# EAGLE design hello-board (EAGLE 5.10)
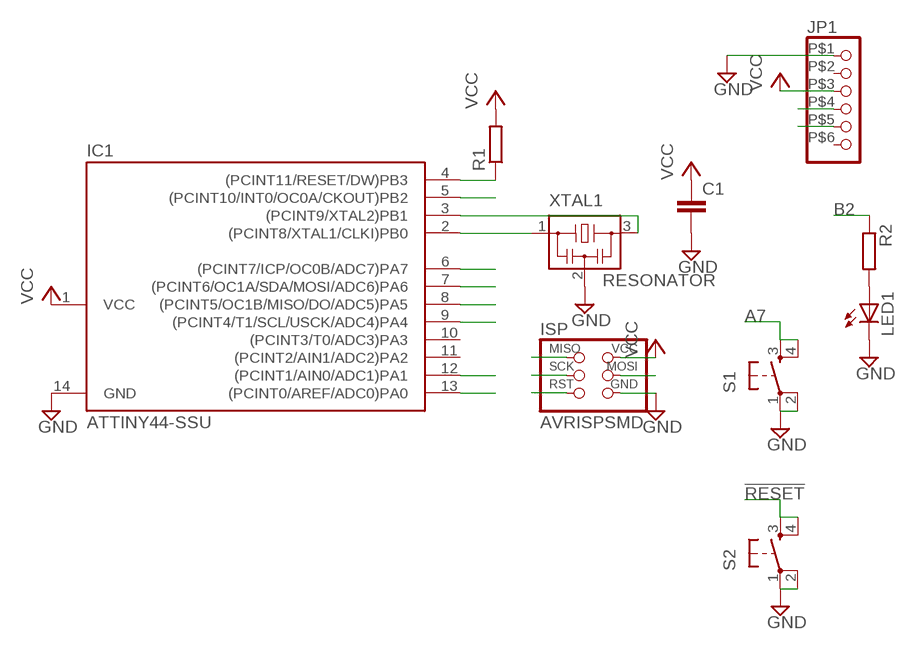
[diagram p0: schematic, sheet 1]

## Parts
C1  C-EUC1206  [C1206]
IC1  ATTINY44-SSU  [SOIC14]
ISP  AVRISPSMD  [2X03SMD]
JP1  PINHD-1X6SMD  [1X06SMD]
LED1  LEDCHIPLED_1206  [CHIPLED_1206]
R1  R-EU_R1206  [R1206]
R2  R-EU_R1206  [R1206]
S1  6MM_SWITCH6MM_SWITCH  [6MM_SWITCH]
S2  6MM_SWITCH6MM_SWITCH  [6MM_SWITCH]
XTAL1  RESONATOR  [EFOBM]

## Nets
!RESET: IC1.4((PCINT11/RESET/DW)PB3) ISP.5(RST) R1.1 S2.3(S) S2.4(S1)
A7: IC1.6((PCINT7/ICP/OC0B/ADC7)PA7) S1.3(S) S1.4(S1)
B2: IC1.5((PCINT10/INT0/OC0A/CKOUT)PB2) R2.1
GND: C1.2 IC1.14(GND) ISP.6(GND) JP1.P$1 LED1.C S1.1(P) S1.2(P1) S2.1(P) S2.2(P1) XTAL1.2
MISO: IC1.8((PCINT5/OC1B/MISO/DO/ADC5)PA5) ISP.1(MISO)
MOSI: IC1.7((PCINT6/OC1A/SDA/MOSI/ADC6)PA6) ISP.4(MOSI)
N$1: LED1.A R2.2
N$2: IC1.2((PCINT8/XTAL1/CLKI)PB0) XTAL1.1
N$3: IC1.3((PCINT9/XTAL2)PB1) XTAL1.3
RX: IC1.12((PCINT1/AIN0/ADC1)PA1) JP1.P$5
SCL: IC1.9((PCINT4/T1/SCL/USCK/ADC4)PA4) ISP.3(SCK)
TX: IC1.13((PCINT0/AREF/ADC0)PA0) JP1.P$4
VCC: C1.1 IC1.1(VCC) ISP.2(VCC) JP1.P$3 R1.2
Unconnected: IC1.10((PCINT3/T0/ADC3)PA3) IC1.11((PCINT2/AIN1/ADC2)PA2) JP1.P$2 JP1.P$6

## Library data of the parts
C1 = rcl:C-EU: CAPACITOR, European symbol
IC1 = fab:ATTINY44
ISP = fab:AVRISP
JP1 = fab-lib:PINHD-1X6: PIN HEADER
LED1 = led:LED: LED
R1 R2 = rcl:R-EU_: RESISTOR, European symbol
S1 S2 = fab:6MM_SWITCH: OMRON SWITCH
XTAL1 = fab:RESONATOR

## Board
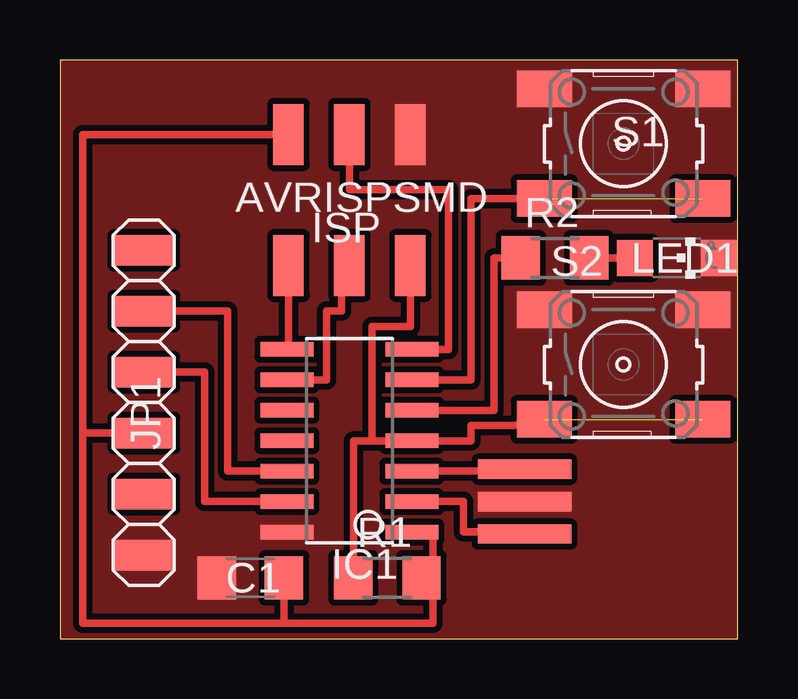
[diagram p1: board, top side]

Size 28.26 x 24.13 mm. Coordinates in mm from the lower left corner, seen from the top.
Outline: 0,0 28.26,0 28.26,24.13 0,24.13 0,0
Copper layers (1*16): Top 0.035mm / dielectric 1.5mm / Bottom 0.035mm
Design rules "default *": minimum track width 10mil, minimum drill 24mil, track to track 10mil, track to pad 10mil, pad to pad 10mil, via to via 10mil, smd to smd 8mil, copper to edge 1mil, drill to drill 8mil, minimum pad ring 10mil, minimum via ring 8mil, stop-mask expansion 4mil, vias tented up to drill 0mil, thermal gap 10mil

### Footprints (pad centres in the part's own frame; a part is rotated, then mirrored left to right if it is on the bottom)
C1206 = smd 1.6 x 1.8: 1 -1.4,0; 2 1.4,0
SOIC14 = smd 0.61 x 2.21: 1 -3.81,-2.603; 2 -2.54,-2.603; 3 -1.27,-2.603; 4 0,-2.603; 5 1.27,-2.603; 6 2.54,-2.603; 7 3.81,-2.603; 8 3.81,2.603; 9 2.54,2.603; 10 1.27,2.603; 11 0,2.603; 12 -1.27,2.603; 13 -2.54,2.603; 14 -3.81,2.603
2X03SMD = smd 2.54 x 1.27: 1 -2.54,2.54; 2 2.92,2.54; 3 -2.54,0; 4 2.92,0; 5 -2.54,-2.54; 6 2.92,-2.54
1X06SMD = smd 1.27 x 2.54: P$1 -6.35,0; P$2 -3.81,0; P$3 -1.27,0; P$4 1.27,0; P$5 3.81,0; P$6 6.35,0
CHIPLED_1206 = smd 1.5 x 1.5: A 0,-1.75; C 0,1.75
R1206 = smd 1.6 x 1.803: 1 -1.422,0; 2 1.422,0
6MM_SWITCH = smd 2.286 x 1.524: 1 -3.302,2.286; 2 3.302,2.286; 3 -3.302,-2.286; 4 3.302,-2.286
EFOBM = smd 0.8 x 3.9: 1 -1.35,0; 2 0,0; 3 1.35,0

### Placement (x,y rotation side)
C1  7.94,2.54 180 top
IC1  12.06,8.26 90 top
ISP  12.06,18.1 90 top
JP1  3.49,9.84 90 top
LED1  25.72,15.88 270 top
R1  13.65,2.54 0 top
R2  20.64,15.88 0 top
S1  23.5,20.64 0 top
S2  23.5,11.43 0 top
XTAL1  19.37,5.71 90 top

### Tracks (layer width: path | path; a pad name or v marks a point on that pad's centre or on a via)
!RESET  (1 unrouted)
  Top 0.305: ISP.5 14.61,13.02 14.14,13.02 13.02,13.02 13.02,8.26 12.23,8.26 | 12.23,8.26 IC1.4 17.15,8.26 17.15,8.89 18.92,8.89 S2.3 | R1.1 12.23,8.26
A7  (1 unrouted)
  Top 0.305: IC1.6 17.15,10.79 17.15,11.75 17.15,18.35 S1.3
B2
  Top 0.305: IC1.5 18.1,9.53 18.1,15.88 R2.1
GND
  pour Top (no thermals): 0,0 28.26,0 28.26,24.13 0,24.13
MISO
  Top 0.305: IC1.8 9.53,12.06 ISP.1
MOSI
  Top 0.305: IC1.7 16.19,12.06 16.19,18.73 13.33,18.73 12.06,18.73 ISP.4
N$1
  Top 0.305: R2.2 LED1.A
N$2
  Top 0.305: IC1.2 16.83,5.71 16.83,4.45 19.37,4.45 XTAL1.1
N$3
  Top 0.305: IC1.3 16.51,6.98 19.37,6.98 XTAL1.3
RX
  Top 0.305: IC1.12 6.98,6.98 6.98,13.65 JP1.P$5
SCL
  Top 0.305: ISP.3 11.75,15.56 11.75,13.65 11.11,13.65 11.11,10.79 IC1.9
TX
  Top 0.305: JP1.P$4 6.03,11.11 6.03,5.71 IC1.13
VCC
  Top 0.305: 9.34,0.64 C1.1 | 9.34,0.64 15.56,0.64 15.56,2.54 | 15.56,2.54 R1.2 | 15.56,2.54 15.56,4.45 IC1.1 | 9.34,0.64 0.95,0.64 0.95,8.57 | 0.95,8.57 JP1.P$3 | 0.95,8.57 0.95,21.02 ISP.2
